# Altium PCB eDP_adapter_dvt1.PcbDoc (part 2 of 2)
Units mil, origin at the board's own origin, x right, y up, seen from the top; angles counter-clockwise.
Board outline 1964.57 x 1377.95 mil, 4 copper layers (Top Layer, Internal Plane 1, Internal Plane 2, Bottom Layer), stack 65.8 mil thick; 112 components, 78 nets, 1150 pads, 214 vias.
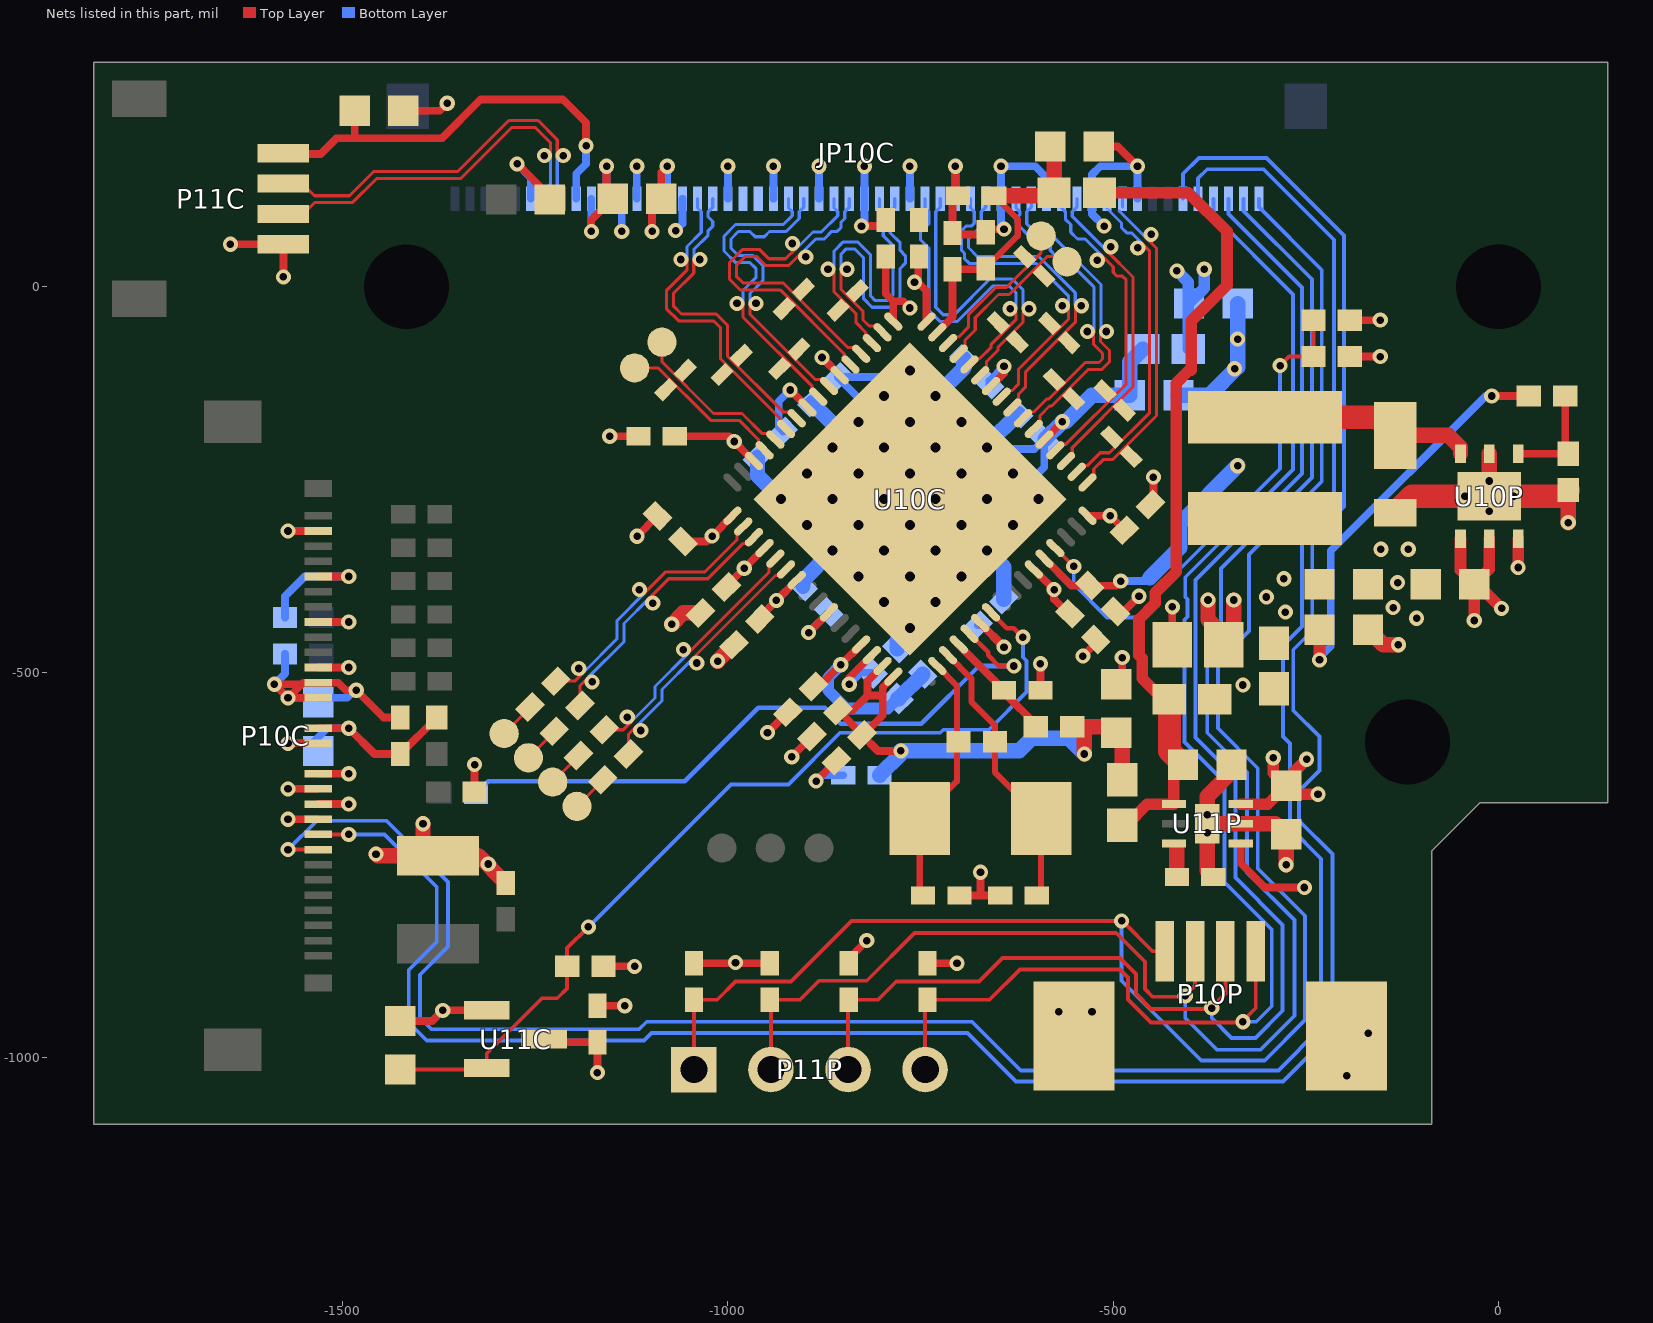
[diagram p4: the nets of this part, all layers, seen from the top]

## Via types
v1: diameter 19.68, hole 9.84, Top Layer to Bottom Layer, tented top, 176 vias
v2: diameter 25.98, hole 12.99, Top Layer to Bottom Layer, tented top, 36 vias
v3: diameter 20, hole 10, Top Layer to Bottom Layer, tented bottom, 2 vias

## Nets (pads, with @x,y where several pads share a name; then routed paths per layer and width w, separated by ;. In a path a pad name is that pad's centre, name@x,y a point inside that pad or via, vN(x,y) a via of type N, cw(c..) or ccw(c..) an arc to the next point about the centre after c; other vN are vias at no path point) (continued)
GND: C10P.1 C11P.1 C12P.2 C13P.2 C14P.1 C15P.1 C16C.2 C16P.1 C17C.1 C17P.1 C18C.1 C18P.1 C19C.1 C19P.1 C20P.1 C21P.1 C22P.1 C23C.2 C23P.1 C24P.1 C25C.2 C25P.1 C26C.2 C26P.1 C27C.2 C27P.1 C28C.2 C29C.2 C30C.2 C31C.2 C32C.2 C33C.2 C34C.2 C35C.2 C36C.2 C37C.2 C38C.2 C39C.2 C40C.2 C41C.2 C42C.2 C43C.2 C44C.2 C45C.2 C46C.2 C47C.2 C48C.2 C49C.1 C50C.1 C51C.2 D10P.1 JP10C.6 JP10C.10 JP10C.11 JP10C.16 JP10C.19 JP10C.22 JP10C.25 JP10C.28 JP10C.31 JP10C.34 JP10C.37 JP10C.40 JP10C.43 JP10C.46 P10C.2 P10C.5 P10C.8 P10C.11 P10C.15 P10C.16 P10C.18 P10C.19 P10C.20 P10C.21 P10P.MP1 P10P.MP2 P11C.1 R10P.2 R17C.2 R25C.2 R31C.2 U10C.65 U10P.2 U10P.7 U11C.1 U11P.2 U11P.PAD | length 4668.8
  Top Layer w10: v1(-1645.67,55.12) P11C.1@-1576.77,55.12 v1(-1576.77,12.8) ; v1(-1570.87,-690.94) P10C.21@-1531.5,-690.94 ; v1(-1570.87,-651.57) P10C.19@-1531.5,-651.57 ; v1(-1570.87,-592.52) P10C.16@-1531.5,-592.52 ; v1(-1570.87,-316.93) P10C.2@-1531.5,-316.93 ; P10C.20@-1531.5,-671.26 v1(-1492.13,-671.26) ; P10C.18@-1531.5,-631.89 v1(-1492.13,-631.89) ; P10C.15@-1531.5,-572.83 v1(-1492.13,-572.83) -1458.66,-606.3 C16C.2@-1425.2,-606.3 R25C.2@-1377.95,-559.06 ; P10C.11@-1531.5,-494.09 v1(-1492.13,-494.09) ; P10C.8@-1531.5,-435.04 v1(-1492.13,-435.04) ; P10C.5@-1531.5,-375.98 v1(-1492.13,-375.98) ; C51C.2@-1425.2,-952.76 -1383.86,-952.76 v1(-1370.08,-938.98) U11C.1@-1312.99,-938.98 ; C49C.1@-1421.26,228.35 -1374.02,228.35 v1(-1364.17,238.19) ; v1(-1273.62,159.45) -1231.3,117.13 C35C.2@-1231.3,113.19 ; v1(-1177.17,71.85) -1177.17,86.61 C50C.1@-1149.61,114.17 -1157.48,122.05 v1(-1157.48,156.5) ; C36C.2@-1169.29,-933.07 v1(-1133.86,-933.07) ; v1(-1153.45,-193.9) C29C.2@-1116.14,-193.9 ; v1(-1117.88,-323.65) C39C.2@-1091.51,-297.27 ; C24P.1@-1044.09,-877.95 C25P.1@-945.67,-877.95 ; v1(-948.59,-578.51) C40C.2@-922.22,-552.14 ; v1(-917.1,-610.01) C46C.2@-890.72,-583.63 ; v1(-885.6,-641.51) C45C.2@-859.22,-615.13 ; C26P.1@-843.31,-877.95 -843.31,-871.85 v1(-819.88,-848.43) ; v1(-826.67,78.74) C30C.2@-789.37,78.74 ; C27P.1@-740.94,-877.95 v1(-702.76,-877.95) ; C48C.2@-708.66,67.91 -666.34,67.91 -659.45,74.8 v1(-641.73,74.8) ; C48C.2@-708.66,69.88 -708.66,111.22 C18P.1@-701.77,118.11 -704.72,121.06 v1(-704.72,156.5) ; C18C.1@-699.52,-790.07 -672.24,-790.07 ; v1(-672.24,-759.84) -672.24,-790.07 ; C19C.1@-646.54,-790.07 -672.24,-790.07 ; C44C.2@-594.49,-523.62 v1(-594.49,-489.17) ; v1(-539.37,-479.33) -522.67,-462.63 C27C.2@-522.67,-457.65 ; C19P.1@-518.7,182.09 -494.09,182.09 v1(-468.5,156.5) ; C25C.2@-491.17,-426.15 v1(-466.59,-401.57) ; C15P.1@-488.19,-515.75 v1(-488.19,-481.3) ; C31C.2@-451.8,-282.51 -447.83,-278.54 v1(-447.83,-247.05) ; C12P.2@-423.23,-464.57 v1(-423.23,-415.35) ; R17C.2@-192.91,-43.31 v1(-153.54,-43.31)
  Top Layer w20: v1(-1456.69,-736.22) -1454.72,-738.19 C23C.2@-1375.98,-738.19 ; v1(-1395.67,-696.85) -1395.67,-718.5 C23C.2@-1375.98,-738.19 ; C34C.2@-1288.39,-773.62 -1323.82,-738.19 C23C.2@-1375.98,-738.19 ; v1(-1072.83,-437.99) -1058.04,-423.2 C41C.2@-1035.4,-423.2 ; v1(-1013.36,-485.8) C43C.2@-992.1,-464.54 ; C16P.1@-370.08,-765.75 -377.95,-757.87 v3(-377.95,-708.66) U11P.PAD@-377.95,-696.85 ; C17P.1@-346.46,-620.08 -346.46,-629.92 -377.95,-661.42 v3(-377.95,-685.04) U11P.PAD@-377.95,-696.85 ; v1(-275.59,-750) C20P.1@-275.59,-710.63 -289.37,-696.85 U11P.2@-334.65,-696.85 U11P.PAD@-377.95,-696.85 ; C11P.1@-169.29,-444.88 -149.61,-464.57 v1(-129.92,-464.57) ; U10P.7@-11.97,-271.78 v1(-11.97,-252.09) U10P.2@-11.97,-216.66 ; v1(90.55,-306.1) R10P.2@90.55,-263.78
  Top Layer w30: D10P.1@-133.86,-293.31 -112.33,-271.78 v1(-43.46,-271.78) U10P.7@-11.97,-271.78 v1(19.53,-271.78) 82.55,-271.78 R10P.2@90.55,-263.78
  Bottom Layer w10: R31C.2@-1574.8,-429.13 -1574.8,-401.57 -1549.21,-375.98 v1(-1492.13,-375.98) ; v1(-1570.87,-592.52) -1539.37,-592.52 -1519.69,-572.83 v1(-1492.13,-572.83) ; v1(-1273.62,159.45) -1255.91,141.73 JP10C.6@-1255.91,114.17 ; v1(-1177.17,71.85) JP10C.10@-1177.17,114.17 ; JP10C.11@-1157.48,114.17 v1(-1157.48,156.5) ; v1(-1067.91,72.83) -1059.06,81.69 JP10C.16@-1059.06,114.17 ; JP10C.19@-1000,114.17 v1(-1000,156.5) ; JP10C.22@-940.94,114.17 v1(-940.94,156.5) ; v1(-885.6,-641.51) -877.95,-633.86 C14P.1@-850.39,-633.86 ; JP10C.25@-881.89,114.17 v1(-881.89,156.5) ; v1(-826.67,78.74) -822.83,82.58 JP10C.28@-822.83,114.17 v1(-822.83,156.5) ; JP10C.31@-763.78,114.17 v1(-763.78,156.5) ; JP10C.34@-704.72,114.17 v1(-704.72,156.5) ; v1(-641.73,74.8) -645.67,78.74 JP10C.37@-645.67,114.17 v1(-645.67,156.5) -601.38,156.5 -586.61,141.73 JP10C.40@-586.61,114.17 ; v1(-511.81,78.74) -527.56,94.49 JP10C.43@-527.56,114.17 -527.56,145.67 -516.73,156.5 v1(-468.5,156.5) JP10C.46@-468.5,114.17
  Bottom Layer w20: C33C.2@-961.59,-221.43 -961.59,-244.82 v2(-930.81,-275.59) ; C42C.2@-902.53,-388.81 -902.53,-380.93 v2(-864,-342.4) ; C37C.2@-890.72,-150.56 -864,-177.28 v2(-864,-208.78) ; C22P.1@-780.48,-469.52 -780.48,-459.33 v2(-763.78,-442.62) ; v2(-730.37,-141.96) -693.87,-105.46 C32C.2@-693.87,-93.53 ; v2(-663.56,-342.4) -641.98,-363.98 C26C.2@-641.98,-405.74 ; v2(-663.56,-208.78) -663.56,-204.96 C38C.2@-623,-164.4 ; C23P.1@-415.35,-140.75 -375,-140.75 -338.58,-104.33 C21P.1@-338.58,-21.65
  other v1: -196.85,-1023.62 -169.29,-968.5 -570.87,-940.94 -527.56,-940.94 -990.16,-876.97 -1311.02,-749.02 -106.3,-430.12 -136.81,-416.34 -130.91,-383.86 -152.56,-340.55 -117.13,-340.55 -11.97,-291.46 -342.52,-106.3 -338.58,-67.91
  other v2: -797.19,-409.22 -730.37,-409.22 -830.59,-375.81 -763.78,-375.81 -696.97,-375.81 -797.19,-342.4 -730.37,-342.4 -897.41,-309 -830.59,-309 -763.78,-309 -696.97,-309 -630.15,-309 -864,-275.59 -797.19,-275.59 -730.37,-275.59 -663.56,-275.59 -596.75,-275.59 -897.41,-242.18 -830.59,-242.18 -763.78,-242.18 -696.97,-242.18 -630.15,-242.18 -797.19,-208.78 -730.37,-208.78 -830.59,-175.37 -763.78,-175.37 -696.97,-175.37 -797.19,-141.96 -763.78,-108.56
GPIO_PWM1: JP10C.50 P10C.23 | length 3031.4
  Top Layer w5: v1(-1570.87,-730.32) P10C.23@-1531.5,-730.32
  Bottom Layer w5: v1(-1570.87,-730.32) -1533.46,-692.91 -1442.91,-692.91 -1363.19,-772.64 -1363.19,-856.3 -1399.61,-892.72 -1399.61,-948.82 -1384.84,-963.58 -1115.16,-963.58 -1105.32,-953.74 -683.07,-953.74 -619.93,-1016.88 -285.58,-1016.88 -230.17,-961.47 -230.17,-742.27 -270.67,-701.77 -270.67,-592.52 -279.53,-583.66 -279.53,-465.55 -254.92,-440.94 -254.92,-320.87 -213.58,-279.53 -213.58,61.02 -305.12,152.56 -377.95,152.56 -389.76,140.75 JP10C.50@-389.76,114.17
I2C_ADR: R16C.2 R17C.1 U10C.13 | length 660.9
  Top Layer w5: U10C.13@-575.17,-338.92 v1(-551.18,-362.91) ; v1(-283.46,-102.36) -271.65,-90.55 R16C.2@-240.16,-90.55 R17C.1@-240.16,-43.31
  Bottom Layer w5: v1(-551.18,-362.91) -551.18,-385.83 -507.87,-429.13 -460.63,-429.13 -444.88,-413.39 -444.88,-397.64 -283.46,-236.22 v1(-283.46,-102.36)
LCD_BL_ON: JP10C.49 P10C.22 | length 3034.5
  Top Layer w5: P10C.22@-1531.5,-710.63 v1(-1492.13,-710.63)
  Bottom Layer w5: v1(-1492.13,-710.63) -1445.87,-710.63 -1377.8,-778.69 -1377.8,-850.25 -1414.22,-886.66 -1414.22,-954.87 -1390.9,-978.2 -1109.1,-978.2 -1099.26,-968.36 -689.12,-968.36 -625.98,-1031.5 -279.53,-1031.5 -215.55,-967.52 -215.55,-736.22 -258.86,-692.91 -258.86,-654.53 -232.28,-627.95 -232.28,-583.66 -266.3,-549.64 -266.3,-471.03 -241.7,-446.42 -241.7,-326.34 -200.36,-285 -200.36,66.5 -301.18,167.32 -388.78,167.32 -409.45,146.65 JP10C.49@-409.45,114.17
LCD_XM: C26P.2 JP10C.52 P10P.3 P11P.3 | length 2035.7
  Top Layer w5: P11P.3@-844.09,-1015.75 -844.09,-925.98 C26P.2@-843.31,-925.2 -805.12,-925.2 -781.5,-901.57 -674.21,-901.57 -643.7,-871.06 -491.14,-871.06 -470.47,-891.73 -470.47,-917.32 -450.79,-937.01 -374.02,-937.01 -354.33,-917.32 P10P.3@-354.33,-862.2
  Bottom Layer w5: v1(-372.05,-936.02) -372.05,-949.21 -346.46,-974.8 -315.35,-974.8 -280.12,-939.57 -280.12,-828.21 -341.54,-766.8 -341.54,-636.81 -393.31,-585.04 -393.31,-380.52 -254.92,-242.13 -254.92,-0.98 -350.39,94.49 JP10C.52@-350.39,114.17
LCD_XP: C24P.2 JP10C.54 P10P.1 P11P.1 | length 2343.1
  Top Layer w5: P11P.1@-1044.09,-1015.75 C24P.2@-1044.09,-925.2 -1013.78,-925.2 -990.16,-901.57 -918.31,-901.57 -839.57,-822.83 -488.19,-822.83 -448.82,-862.2 P10P.1@-433.07,-862.2
  Bottom Layer w5: v1(-489.17,-822.83) -489.17,-900.59 -385.83,-1003.94 -303.28,-1003.94 -250.98,-951.64 -250.98,-816.14 -312.4,-754.73 -312.4,-624.74 -364.17,-572.97 -364.17,-487.2 -323.82,-446.85 -323.82,-347.21 -229.33,-252.73 -229.33,21.65 -311.02,103.35 JP10C.54@-311.02,114.17
LCD_YM: C27P.2 JP10C.51 P10P.4 P11P.4 | length 1905
  Top Layer w5: P11P.4@-744.09,-1015.75 -744.09,-928.35 C27P.2@-740.94,-925.2 -660.43,-925.2 -621.06,-885.83 -491.14,-885.83 -480.81,-896.16 -480.81,-924.7 -450.79,-954.72 -333.66,-954.72 -314.96,-936.02 P10P.4@-314.96,-862.2
  Bottom Layer w5: JP10C.51@-370.08,114.17 -370.08,93.5 -266.73,-9.84 -266.73,-237.23 -406.5,-377 -406.5,-402.56 -403.54,-405.51 -403.54,-428.15 -407.48,-432.09 -407.48,-590.9 -355.7,-642.68 -355.7,-772.67 -294.29,-834.08 -294.29,-933.7 -314.33,-953.74 v1(-331.69,-953.74)
LCD_YP: C25P.2 JP10C.53 P10P.2 P11P.2 | length 2190.1
  Top Layer w5: P11P.2@-944.09,-1015.75 -944.09,-926.77 C25P.2@-945.67,-925.2 -906.5,-925.2 -881.89,-900.59 -819.88,-900.59 -757.87,-838.58 -496.06,-838.58 -458.66,-875.98 -458.66,-911.42 -448.82,-921.26 -408.46,-921.26 -393.7,-906.5 P10P.2@-393.7,-862.2
  Bottom Layer w5: v1(-406.5,-920.28) -406.5,-948.82 -365.16,-990.16 -308.99,-990.16 -264.76,-945.93 -264.76,-821.85 -326.18,-760.44 -326.18,-630.45 -377.95,-578.67 -377.95,-479.33 -360.24,-461.61 -360.24,-365.54 -242.13,-247.43 -242.13,9.84 -330.71,98.43 JP10C.53@-330.71,114.17
LVDS0_CLK_N: JP10C.36 R11C.2 U10C.24 | length 418.1
  Top Layer w4.02: U10C.24@-630.85,-156.58 -622.7,-148.43 -622.7,-139.11 -614.02,-130.42 -614.02,-111.02 -549.06,-46.06 v1@-549.06,-23.62
  Bottom Layer w4.02: JP10C.36@-665.35,114.17 -665.35,103.35 -671.26,97.44 -671.26,78.79 -687.83,62.21 -687.83,50.98 -676.23,39.37 -596.5,39.37 -549.21,-7.92 v1@-549.21,-23.62
  other v1: -541.34,-24.61
LVDS0_CLK_P: JP10C.35 R11C.1 U10C.25 | length 417.2
  Top Layer w4.02: U10C.25@-644.77,-142.66 -636.81,-134.7 -631.05,-134.7 -623.03,-126.69 -623.03,-107.28 -558.07,-42.32 v1@-558.07,-23.62
  Bottom Layer w4.02: JP10C.35@-685.04,114.17 -685.04,102.2 -680.28,97.44 -680.28,82.52 -684.06,78.74 -690.95,78.74 -694.88,74.8 -694.88,67.91 -696.85,65.94 -696.85,47.24 -692.91,43.31 -692.91,36.42 -686.85,30.35 -600.24,30.35 -558.23,-11.65 v1@-558.23,-23.62
  other v1: -565.94,-24.61
LVDS0_TX_0_N: JP10C.45 R14C.2 U10C.17 | length 426.9
  Top Layer w4.02: U10C.17@-533.41,-254.02 -525.27,-245.87 -525.27,-236.55 -513.13,-224.41 -500.98,-224.41 -474.41,-197.83 -443.74,-167.16 -443.74,49.99 v1@-455.24,61.49
  Bottom Layer w4.02: -492.13,98.43 v1@-455.71,62.01 ; JP10C.45@-488.19,103.35 JP10C.45@-488.19,114.17
  other v1: -450.79,67.91
LVDS0_TX_0_P: JP10C.44 R14C.1 U10C.18 | length 425.3
  Top Layer w4.02: U10C.18@-547.33,-240.1 -539.38,-232.14 -533.61,-232.14 -516.86,-215.39 -504.72,-215.39 -452.76,-163.43 -452.76,46.26 v1@-461.61,55.12
  Bottom Layer w4.02: JP10C.44@-507.87,102.2 JP10C.44@-507.87,114.17 ; JP10C.44@-505.39,98.94 -489.17,82.72 -489.17,76.77 -482.31,69.9 -476.36,69.9 v1@-462.08,55.63
  other v1: -468.19,50.51
LVDS0_TX_1_N: JP10C.42 R13C.2 U10C.19 | length 410.1
  Top Layer w4.02: U10C.19@-561.25,-226.18 -553.1,-218.03 -553.1,-208.71 -474.25,-129.85 -474.25,12.64 v1@-507.87,46.26
  Bottom Layer w4.02: JP10C.42@-547.24,114.17 -547.24,103.35 -553.15,97.44 -553.15,91.54 v1@-508.86,47.24
  other v1: -503.27,51.85
LVDS0_TX_1_P: JP10C.41 R13C.1 U10C.20 | length 411
  Top Layer w4.02: U10C.20@-575.17,-212.26 -567.21,-204.3 -561.45,-204.3 -483.27,-126.12 -483.27,8.9 -488.19,13.82 -495.12,13.82 -499.98,18.68 -499.98,25.61 v1@-514.25,39.88
  Bottom Layer w4.02: JP10C.41@-566.93,114.17 -566.93,102.2 -562.17,97.44 -562.17,87.8 -555.12,80.75 -555.12,70.87 -546.26,62.01 -536.37,62.01 v1@-515.23,40.87
  other v1: -520.67,34.45
LVDS0_TX_2_N: JP10C.39 R12C.2 U10C.22 | length 410.8
  Top Layer w4.02: U10C.22@-603.01,-184.42 -594.86,-176.27 -594.86,-166.95 -582.6,-154.69 -579.93,-154.69 -540.94,-115.7 -532.53,-107.28 -514.76,-107.28 -504.92,-97.44 -504.92,-82.68 -516.57,-71.02 v1@-516.57,-57.09
  Bottom Layer w4.02: JP10C.39@-606.3,114.17 -606.3,103.35 -612.2,97.44 -612.2,81.65 -603.39,72.83 -585.67,72.83 -515.75,2.91 v1@-515.75,-59.06
  other v1: -508.86,-58.07
LVDS0_TX_2_P: JP10C.38 R12C.1 U10C.23 | length 410.9
  Top Layer w4.02: U10C.23@-616.93,-170.5 -608.97,-162.54 -603.21,-162.54 -586.33,-145.67 -583.66,-145.67 -547.31,-109.32 -536.26,-98.27 -518.5,-98.27 -513.94,-93.71 -513.94,-86.41 -525.59,-74.76 v1@-525.59,-57.09
  Bottom Layer w4.02: JP10C.38@-625.98,114.17 -625.98,102.2 -621.22,97.44 -621.22,93.35 -625.98,88.58 -625.98,82.68 -607.13,63.82 -589.41,63.82 -581.69,56.1 -581.69,47.24 -574.8,40.35 -565.94,40.35 -524.76,-0.83 v1@-524.76,-59.06
  other v1: -533.46,-58.07
LVDS0_TX_3_N: JP10C.33 R10C.2 U10C.27 | length 413.3
  Top Layer w4.02: U10C.27@-672.61,-114.82 -664.46,-106.67 -664.46,-97.35 -649.45,-82.34 -649.45,-78.54 -616.97,-46.06 v1@-616.97,-33.46
  Bottom Layer w4.02: JP10C.33@-724.41,114.17 -724.41,103.35 -730.31,97.44 -730.31,32.68 -730.31,-26.57 -720.63,-36.26 -706.49,-36.26 -660.23,10 -631.11,10 -617.13,-3.98 v1@-617.13,-27.56
  other v1: -609.25,-28.54
LVDS0_TX_3_P: JP10C.32 R10C.1 U10C.28 | length 413.2
  Top Layer w4.02: U10C.28@-686.53,-100.9 -678.57,-92.94 -672.8,-92.94 -658.46,-78.61 -658.46,-74.8 -625.98,-42.32 v1@-625.98,-33.46
  Bottom Layer w4.02: JP10C.32@-744.09,114.17 -744.09,102.2 -739.33,97.44 -739.33,81.54 -750,70.87 -750,60.87 -739.33,50.2 -739.33,-30.31 -724.36,-45.28 -702.76,-45.28 -656.5,0.98 -634.84,0.98 -626.14,-7.72 v1@-626.14,-27.56
  other v1: -633.86,-28.54
LVDS1_CLK_N: JP10C.21
LVDS1_CLK_P: JP10C.20
LVDS1_TX0_N: JP10C.30 R18C.1 U10C.34 | length 416.2
  Top Layer w4.02: v1@-853.19,20.67 -853.19,-3.16 -824.65,-31.7 -824.65,-43.1 -816.74,-51 -807.42,-51 U10C.34@-799.27,-59.14
  Bottom Layer w4.02: v1@-853.35,22.64 -853.35,42.32 -846.46,49.21 -835.63,49.21 -823.82,37.4 -823.82,-15.75 -812.99,-26.57 -789.37,-26.57 -776.57,-13.78 -776.57,23.62 -769.69,30.51 -769.69,40.35 -776.57,47.24 -776.57,57.09 -789.37,69.88 -789.37,97.44 -783.46,103.35 JP10C.30@-783.46,114.17
  other v1: -845.47,22.64
LVDS1_TX0_P: JP10C.29 R18C.2 U10C.35 | length 416.4
  Top Layer w4.02: v1@-862.2,20.67 -862.2,-6.89 -833.66,-35.43 -833.66,-46.83 -821.15,-59.34 -821.15,-65.11 U10C.35@-813.19,-73.06
  Bottom Layer w4.02: v1@-862.36,22.64 -862.36,46.06 -850.19,58.23 -831.9,58.23 -814.8,41.14 -814.8,12.8 -814.8,-12.01 -809.26,-17.56 -793.1,-17.56 -785.59,-10.05 -785.59,53.35 -798.39,66.15 -798.39,97.44 -803.15,102.2 JP10C.29@-803.15,114.17
  other v1: -870.08,22.64
LVDS1_TX1_N: JP10C.27 R19C.1 U10C.36 | length 425.1
  Top Layer w4.02: v1@-905.04,43.82 -921.46,27.4 -950.63,27.4 -962.44,39.21 -977.56,39.21 -989.02,27.76 -989.02,13.58 -980.52,5.08 -928.5,5.08 -844.58,-78.84 -835.26,-78.84 U10C.36@-827.11,-86.98
  Bottom Layer w4.02: v1@-904.55,43.33 -885.87,62.01 -875.05,62.01 -865.2,71.85 -858.27,71.85 -853.35,76.77 -853.35,83.71 -848.43,88.63 -848.43,97.44 -842.52,103.35 JP10C.27@-842.52,114.17
  other v1: -898.94,38.7
LVDS1_TX1_P: JP10C.26 R19C.2 U10C.37 | length 427
  Top Layer w4.02: v1@-911.42,50.2 -925.2,36.42 -946.9,36.42 -958.71,48.23 -981.3,48.23 -998.03,31.5 -998.03,9.84 -984.25,-3.94 -932.23,-3.94 -848.99,-87.18 -848.99,-92.94 U10C.37@-841.03,-100.9
  Bottom Layer w4.02: v1@-910.93,49.7 -889.61,71.02 -878.78,71.02 -857.44,92.36 -857.44,97.44 -862.2,102.2 JP10C.26@-862.2,114.17
  other v1: -916.34,56.1
LVDS1_TX2_N: JP10C.24 R20C.1 U10C.39 | length 408.7
  Top Layer w4.02: v1@-971.3,-20.67 -971.3,-35.64 -886.34,-120.59 -877.02,-120.59 U10C.39@-868.87,-128.74
  Bottom Layer w4.02: v1@-971.3,-22.64 -971.3,-8.66 -954.72,7.92 -954.72,27.56 -967.52,40.35 -986.22,40.35 -996.06,50.2 -996.06,62.01 -986.38,71.69 -971.46,71.69 -964.72,64.96 -952.76,64.96 -946.02,71.69 -924.42,71.69 -907.48,88.63 -907.48,97.44 -901.57,103.35 JP10C.24@-901.57,114.17
  other v1: -963.58,-21.65
LVDS1_TX2_P: JP10C.23 R20C.2 U10C.40 | length 409.1
  Top Layer w4.02: v1@-980.32,-20.67 -980.32,-39.37 -890.75,-128.94 -890.75,-134.7 U10C.40@-882.79,-142.66
  Bottom Layer w4.02: v1@-980.32,-22.64 -980.32,-4.92 -963.74,11.65 -963.74,23.82 -971.25,31.34 -989.95,31.34 -1005.08,46.46 -1005.08,65.74 -990.11,80.71 -928.15,80.71 -916.5,92.36 -916.5,97.44 -921.26,102.2 JP10C.23@-921.26,114.17
  other v1: -988.19,-21.65
LVDS1_TX_3_N: JP10C.18 R21C.1 U10C.42 | length 407.1
  Top Layer w4.02: v1@-1044.29,34.45 -1044.29,17.76 -1070.87,-8.81 -1070.87,-24.65 -1060.24,-35.28 -1014.97,-35.28 -1000.44,-49.8 -1000.44,-90.01 -928.1,-162.35 -918.78,-162.35 U10C.42@-910.63,-170.5
  Bottom Layer w4.02: v1@-1044.13,36.42 -1044.13,48.43 -1025.59,66.97 -1025.59,72.83 -1019.69,78.74 -1019.69,84.65 -1025.59,90.55 -1025.59,97.44 -1019.69,103.35 JP10C.18@-1019.69,114.17
  other v1: -1036.42,35.43
LVDS1_TX_3_P: JP10C.17 R21C.2 U10C.43 | length 408.1
  Top Layer w4.02: v1@-1053.31,34.45 -1053.31,21.5 -1079.88,-5.08 -1079.88,-28.39 -1063.98,-44.29 -1018.7,-44.29 -1009.46,-53.53 -1009.46,-93.74 -1006.82,-96.38 -932.51,-170.7 -932.51,-176.46 U10C.43@-924.55,-184.42
  Bottom Layer w4.02: v1@-1053.15,36.42 -1053.15,52.17 -1034.61,70.71 -1034.61,97.44 -1039.37,102.2 JP10C.17@-1039.37,114.17
  other v1: -1061.02,35.43
NetC16P_2: C16P.2 U11P.6 | length 35.4
  Top Layer w20: C16P.2@-417.32,-765.75 -417.32,-730.32
NetC18C_2: C18C.2 R28C.2 U10C.2 Y10C.1 | length 330.3
  Top Layer w8: C18C.2@-746.76,-790.07 -750.98,-785.85 Y10C.1@-750.98,-689.85 -702.76,-641.63 -702.76,-517.57 U10C.2@-728.28,-492.04
NetC19C_2: C19C.2 R28C.1 U10C.3 Y10C.2 | length 364.4
  Top Layer w8: U10C.3@-714.37,-478.12 -684.06,-508.43 -684.06,-538.39 -653.54,-568.9 R28C.1@-653.54,-590.55 -653.54,-629.81 Y10C.2@-593.5,-689.85 -593.5,-784.27 C19C.2@-599.3,-790.07
NetC20C_2: C20C.2 J17C.1 | length 48.4
  Top Layer w4.02: J17C.1@-1290.35,-579.72 -1256.86,-546.23 C20C.2@-1256.86,-545.25
NetC21C_2: C21C.2 J18C.1 | length 48.4
  Top Layer w4.02: J18C.1@-1258.86,-611.22 -1225.36,-577.73 C21C.2@-1225.36,-576.74
NetC22C_1: C22C.1 J19C.1 | length 48.4
  Top Layer w4.02: J19C.1@-1195.87,-674.21 -1162.37,-640.72 C22C.1@-1162.37,-639.73
NetC24C_1: C24C.1 J20C.1 | length 48.4
  Top Layer w4.02: J20C.1@-1227.36,-642.72 -1193.87,-609.22 C24C.1@-1193.87,-608.24
NetC44C_1: C44C.1 R27C.2 U10C.4 | length 156.2
  Top Layer w10: U10C.4@-700.45,-464.2 -700.45,-464.91 C44C.1@-641.73,-523.62 -641.73,-526.57 -597.44,-570.87 R27C.2@-590.55,-570.87
NetD10P_2: D10P.2 L11P.1 U10P.3 | length 278.2
  Top Layer w20: D10P.2@-133.86,-192.91 -64.96,-192.91 -49.37,-208.5 U10P.3@-49.37,-216.66
  Top Layer w30: L11P.1@-303.15,-169.29 -157.48,-169.29 D10P.2@-133.86,-192.91
NetJ10C_1: J10C.1 R15C.2 U10C.29 | length 210.5
  Top Layer w4.02: U10C.29@-700.45,-86.98 -692.3,-78.84 -692.3,-69.51 -678.98,-56.19 -678.98,-40.15 -648.82,-10 -635,-10 -585.63,39.37 -566.93,39.37 J10C.1@-560.04,32.48
NetJ11C_1: J11C.1 R15C.1 U10C.30 | length 200.5
  Top Layer w4.02: U10C.30@-714.37,-73.06 -706.41,-65.11 -700.64,-65.11 -687.99,-52.46 -687.99,-36.42 -652.56,-0.98 -638.73,-0.98 -593.5,44.25 J11C.1@-593.5,65.94
NetJ14C_1: J14C.1 R22C.2 U10C.44 | length 214.5
  Top Layer w4.02: J14C.1@-1085.63,-71.85 -1085.63,-97.44 -1018.7,-164.37 -981.76,-164.37 -955.94,-190.19 -946.62,-190.19 U10C.44@-938.47,-198.34
NetJ16C_1: J16C.1 R22C.1 U10C.45 | length 216.3
  Top Layer w4.02: J16C.1@-1121.06,-105.32 -1090.51,-105.32 -1022.44,-173.39 -985.49,-173.39 -960.35,-198.53 -960.35,-204.3 U10C.45@-952.39,-212.26
NetR10P_1: R10P.1 R11P.2 U10P.1 | length 141.5
  Top Layer w10: U10P.1@25.43,-216.66 90.43,-216.66 86.61,-212.85 R11P.2@86.61,-141.73
NetR23C_1: R23C.1 U10C.62 | length 85.4
  Top Layer w10: v1(-842.52,-515.75) -842.52,-507.44 U10C.62@-813.19,-478.12
  Bottom Layer w10: v1(-842.52,-515.75) -827.78,-501.01 R23C.1@-812.96,-501.01
NetR29C_1: R29C.1 U10C.5 | length 860.7
  Top Layer w6: U10C.5@-686.53,-450.28 -662.4,-474.4 -662.4,-478.35 -648.62,-492.13 v1(-628.94,-492.13)
  Bottom Layer w6: R29C.1@-1326.77,-657.48 -1311.02,-641.73 -1056.1,-641.73 -960.63,-546.26 -874.02,-546.26 -853.35,-566.93 -749.02,-566.93 -674.21,-492.13 v1(-628.94,-492.13)
P1.8VA: C12P.1 C22P.2 C30C.1 C31C.1 C32C.1 C33C.1 C39C.1 C40C.1 C41C.1 C42C.1 C43C.1 L10P.1 L12P.2 R23C.2 U10C.16 U10C.26 U10C.33 U10C.41 U10C.49 U10C.52 U10C.55 U10C.58 U10C.61 | length 1028.1
  Top Layer w10: C39C.1@-1058.1,-330.68 -1027.66,-330.68 v1(-1020.52,-323.54) U10C.49@-994.15,-297.17 ; C41C.1@-1002,-389.79 -1002,-388.53 v1(-978.77,-365.3) U10C.52@-952.39,-338.92 ; C43C.1@-958.69,-431.13 -958.69,-428.74 v1(-937.01,-407.06) U10C.55@-910.63,-380.68 ; v1(-919.29,-134) U10C.41@-896.71,-156.58 ; v1(-895.25,-448.82) U10C.58@-868.87,-422.44 ; C40C.1@-888.81,-518.73 -881.64,-518.73 v1(-853.49,-490.58) U10C.61@-827.11,-464.2 ; C30C.1@-795.28,39.37 -795.28,-8.86 -785.35,-18.78 ; U10C.33@-785.35,-45.22 -785.35,-18.78 ; v1(-763.78,-27.56) -772.56,-18.78 -785.35,-18.78 ; U10C.26@-658.69,-128.74 -658.27,-128.74 -641.73,-112.2 v1(-641.73,-103.35) ; U10C.16@-533.41,-297.17 v1(-503.96,-297.17) C31C.1@-485.21,-315.92
  Top Layer w20: v1(-376.97,-406.5) -376.97,-432.09 -356.3,-452.76 C12P.1@-356.3,-464.57 -343.5,-451.77 v1(-343.5,-406.5)
  Bottom Layer w10: C33C.1@-928.18,-188.02 -934.06,-182.14 -934.06,-148.76 v1(-919.29,-134) ; v1(-895.25,-448.82) -895.25,-448.34 C42C.1@-869.12,-422.22 ; C32C.1@-660.46,-126.94 -660.46,-122.08 v1(-641.73,-103.35)
  Bottom Layer w15: v1(-853.49,-490.58) -870.08,-507.16 -870.08,-523.62 -846.46,-547.24 -792.38,-547.24 R23C.2@-779.56,-534.42
  Bottom Layer w20: R23C.2@-779.56,-534.42 -778.57,-534.42 C22P.2@-747.08,-502.92
  other v1: -331.69,-516.73
P1.8VA_DP_PLL: C14P.2 C15P.2 C45C.1 C46C.1 L13P.2 R27C.1 U10C.63 U10C.64 | length 764
  Top Layer w10: C46C.1@-857.31,-550.23 C46C.1@-856.33,-550.23 ; U10C.63@-799.27,-492.04 -818.9,-511.66 -818.9,-530.51 ; U10C.64@-785.35,-505.96 -799.21,-519.82 -799.21,-532.48 ; v1(-775.59,-602.36) -805.18,-602.36 C45C.1@-825.82,-581.72 C45C.1@-824.83,-581.72 ; C15P.2@-496.06,-570.87 C15P.2@-488.19,-578.74 ; C46C.1@-856.33,-550.23 -838.61,-550.23 -818.9,-530.51 ; C46C.1@-856.33,-550.23 C45C.1@-824.83,-581.72 ; C45C.1@-824.83,-581.72 -799.21,-556.1 -799.21,-532.48 ; -818.9,-530.51 -801.18,-530.51 -799.21,-532.48
  Top Layer w20: v1(-537.4,-606.3) -537.4,-576.77 -543.31,-570.87 C15P.2@-496.06,-570.87 ; L13P.2@-488.19,-639.76 C15P.2@-488.19,-578.74
  Bottom Layer w20: C14P.2@-803.15,-633.86 -775.59,-606.3 v1(-775.59,-602.36) -622.05,-602.36 -605.32,-585.63 -558.07,-585.63 v1(-537.4,-606.3)
P1.8VA_LVDS_PLL: C18P.2 C19P.2 C47C.1 C48C.1 L14P.2 U10C.31 | length 399.4
  Top Layer w8: C47C.1@-665.35,23.62 -665.35,24.61 -623.89,66.07 -623.89,87.47 C18P.2@-654.53,118.11
  Top Layer w10: U10C.31@-728.28,-59.14 -708.66,-39.52 C48C.1@-708.66,22.64 -666.34,22.64 C47C.1@-665.35,23.62
  Top Layer w20: C18P.2@-654.53,118.11 -580.71,118.11 L14P.2@-576.77,122.05 -576.77,177.17 C19P.2@-581.69,182.09
P1.8VA_REG: C17P.2 L10P.2 L13P.1 L14P.1 U11P.4 | length 1089.8
  Top Layer w15: L14P.1@-517.72,122.05 -402.56,122.05 -352.36,71.85 -352.36,1.97 -398.62,-44.29 -398.62,-108.27 -401.57,-108.27 -418.31,-125 -418.31,-370.08 -445.25,-397.02 -445.25,-410.42 -466.54,-431.7 -466.54,-478.35 -462.6,-482.28 -462.6,-507.87 -435.04,-535.43 L10P.2@-427.17,-535.43 ; L13P.1@-488.19,-698.82 -483.27,-698.82 -455.71,-671.26 U11P.4@-421.26,-671.26 -421.26,-631.89 C17P.2@-409.45,-620.08
  Top Layer w30: L10P.2@-427.17,-535.43 -427.17,-602.36 C17P.2@-409.45,-620.08
P1.8VD: C10P.2 C11P.2 C26C.1 C27C.1 C28C.1 C29C.1 L11P.2 L12P.1 R11P.1 U10C.6 U10C.11 U10C.32 U10C.46 | length 901.3
  Top Layer w10: C29C.1@-1068.9,-193.9 -998.59,-193.9 U10C.46@-966.31,-226.18 ; C28C.1@-751.97,39.37 -752.95,38.39 -752.95,4.92 -742.2,-5.83 U10C.32@-742.2,-45.22 ; U10C.6@-672.61,-436.36 -672.61,-436.64 v1(-641.73,-467.52) ; U10C.11@-603.01,-366.76 v1(-576.77,-393) -576.77,-405.51 -558.04,-424.24 C27C.1@-556.07,-424.24 ; v1(-8.86,-141.73) R11P.1@39.37,-141.73
  Top Layer w15: v1(-232.28,-484.25) C11P.2@-232.28,-444.88
  Bottom Layer w10: C26C.1@-675.39,-439.14 -670.11,-439.14 v1(-641.73,-467.52) ; v1@-235.24,-484.25 -217.52,-466.54 -217.52,-342.52 -16.73,-141.73 v1(-8.86,-141.73)
  other v1: -276.57,-422.24 -301.18,-402.56 -278.54,-378.94 -991.7,-200.79 -757.87,5.91
P3.3V: C13P.1 C16C.1 C17C.2 C20P.2 C21P.2 C25C.1 C36C.1 C50C.2 JP10C.12 JP10C.13 JP10C.14 JP10C.15 L15P.1 P10C.12 P10C.13 R16C.1 R24C.1 R26C.1 R30C.2 U10C.12 U10P.4 U10P.5 U10P.6 U11C.3 U11P.1 U11P.3 | length 1995.2
  Top Layer w10: P10C.13@-1531.5,-533.46 v1(-1570.87,-533.46) ; C16C.1@-1425.2,-559.06 -1446.85,-559.06 v1(-1482.28,-523.62) -1496.06,-523.62 -1505.91,-513.78 P10C.12@-1531.5,-513.78 -1551.18,-513.78 -1555.12,-517.72 ; R24C.1@-1328.74,-655.51 v1(-1328.74,-620.08) ; U11C.3@-1238.19,-976.38 -1234.25,-980.31 C36C.1@-1169.29,-980.31 v1(-1169.29,-1019.68) ; R26C.1@-1161.42,-881.89 v1(-1121.06,-881.89) ; v1(-1098.43,71.85) -1098.43,102.36 C50C.2@-1086.61,114.17 -1086.61,148.62 v1(-1078.74,156.5) ; U10C.12@-589.09,-352.84 -554.14,-387.8 -496.06,-387.8 v1(-490.16,-381.89) ; U11P.1@-334.65,-722.44 -334.65,-748.03 -303.15,-779.53 v1(-251.97,-779.53) ; R16C.1@-192.91,-90.55 v1(-153.54,-90.55) ; v1(-1570.87,-533.46) v1(-1588.58,-515.75) -1557.09,-515.75 -1555.12,-517.72 ; v1(-1570.87,-533.46) -1555.12,-517.72
  Top Layer w15: U11P.3@-334.65,-671.26 -299.21,-671.26 C20P.2@-275.59,-647.64 ; v1(-292.32,-611.22) -292.32,-630.91 C20P.2@-275.59,-647.64 ; v1(-249.02,-613.19) -275.59,-639.76 C20P.2@-275.59,-647.64 ; v1(-234.25,-658.46) -264.76,-658.46 C20P.2@-275.59,-647.64 ; U10P.4@-49.37,-326.9 -49.37,-367.95 C13P.1@-31.5,-385.83 ; v1(-31.5,-433.07) C13P.1@-31.5,-385.83 ; U10P.5@-11.97,-326.9 -11.97,-366.3 C13P.1@-31.5,-385.83 ; v1(3.94,-417.32) -27.56,-385.83 C13P.1@-31.5,-385.83 ; v1(25.43,-364.33) U10P.6@25.43,-326.9
  Bottom Layer w10: v1(-1588.58,-515.75) -1574.8,-501.97 R30C.2@-1574.8,-476.38 ; v1(-1570.87,-533.46) -1494.09,-533.46 -1484.25,-523.62 v1(-1482.28,-523.62) ; v1(-1137.8,71.85) JP10C.12@-1137.8,114.17 ; JP10C.13@-1118.11,114.17 v1(-1118.11,156.5) ; v1(-1098.43,71.85) JP10C.14@-1098.43,114.17 ; JP10C.15@-1078.74,114.17 v1(-1078.74,156.5) ; v1(-490.16,-381.89) -456.69,-381.89 -452.76,-377.95
  Bottom Layer w15: v1(-417.32,20.67) -402.56,5.91 L15P.1@-402.56,-80.71 ; C21P.2@-401.57,-21.65 -381.89,-1.97 v1(-381.89,22.64)
  Bottom Layer w20: -452.76,-377.95 -413.39,-338.58 -413.39,-307.09 v1(-338.58,-232.28)
P3.3VA: C23P.2 C37C.1 C38C.1 L15P.2 U10C.21 U10C.38 | length 1275.5
  Top Layer w10: v1(-877.95,-91.82) U10C.38@-854.95,-114.82 ; U10C.21@-589.09,-198.34 v1(-565.95,-175.19)
  Bottom Layer w10: v1(-877.95,-91.82) -857.31,-112.46 C37C.1@-857.31,-117.15 ; C38C.1@-588.56,-197.81 C38C.1@-589.6,-197.81 ; v1(-565.95,-175.19) v1@-562.06,-175.19 ; C37C.1@-857.31,-117.15 -796.32,-178.15 ; C37C.1@-857.31,-117.15 -789.34,-117.15 -772.89,-133.61 -772.89,-153.38 ; -796.32,-178.15 -796.32,-176.81 -772.89,-153.38 ; -796.32,-178.15 -775.19,-199.27 -754.39,-199.27 ; -772.89,-153.38 -752.13,-153.38 -730.32,-175.2 ; -754.39,-199.27 -730.32,-175.2 ; -754.39,-199.27 -754.39,-218.05 -729.33,-243.11 ; -730.32,-175.2 -694.39,-211.12 ; -729.33,-243.11 -697.34,-211.12 -694.39,-211.12 ; -729.33,-243.11 -708.26,-264.18 -685.44,-264.18 ; -694.39,-211.12 -663.39,-242.13 ; -685.44,-264.18 -663.39,-242.13 ; -685.44,-264.18 -685.55,-264.29 -685.55,-278.54 -685.55,-287.87 -675.84,-297.58 -654.45,-297.58 -631.89,-275.02 -631.89,-264.18 ; -663.39,-242.13 -631.89,-210.63 -602.42,-210.63 C38C.1@-589.6,-197.81 ; -663.39,-242.13 -641.34,-264.18 -631.89,-264.18 ; -631.89,-264.18 -619.49,-264.18 -589.6,-234.28 C38C.1@-589.6,-197.81
  Bottom Layer w20: C38C.1@-588.56,-197.81 v1(-565.95,-175.19) ; v1@-562.06,-175.19 -527.62,-140.75 C23P.2@-478.35,-140.75 -478.35,-97.44 L15P.2@-461.61,-80.71
RESET_N: C51C.1 R26C.2 U10C.7 U11C.2 | length 1185.1
  Top Layer w5: C51C.1@-1425.2,-1015.75 -1314.96,-1015.75 U11C.2@-1312.99,-1013.78 -1312.99,-995.08 -1241.14,-923.23 -1221.46,-923.23 -1208.66,-910.43 R26C.2@-1208.66,-881.89 -1208.66,-858.27 v1(-1181.1,-830.71)
  Top Layer w6: U10C.7@-658.69,-422.44 -638.22,-442.91 -628.94,-442.91 v1(-617.13,-454.72)
  Bottom Layer w5: v1(-1181.1,-830.71) -996.06,-645.67 -921.26,-645.67 -854.33,-578.74 -724.41,-578.74 -720.47,-574.8 -661.42,-574.8 -612.59,-525.98 -612.59,-485.36 -617.13,-480.83 v1(-617.13,-454.72)
TX2_N: C24C.2 U10C.53 | length 325.7
  Top Layer w4.02: C24C.2@-1160.46,-574.83 -1135.81,-574.83 v1@-1125.47,-564.49 ; v1@-1050.95,-474.64 -946.62,-370.31 -946.62,-360.99 U10C.53@-938.47,-352.84
  Bottom Layer w4.02: v1@-1124.49,-563.51 -1094.65,-533.67 -1094.65,-518.82 v1@-1051.49,-475.66
  other v1: -1130.59,-558.39 -1057.75,-470.79
TX2_P: C22C.2 U10C.54 | length 325
  Top Layer w4.02: C22C.2@-1128.97,-606.33 -1128.97,-580.74 v1@-1119.09,-570.87 ; v1@-1044.57,-481.02 -938.27,-374.72 -932.51,-374.72 U10C.54@-924.55,-366.76
  Bottom Layer w4.02: v1@-1118.11,-569.88 -1085.63,-537.4 -1085.63,-522.55 v1@-1045.11,-482.04
  other v1: -1113.19,-575.79 -1040.35,-488.19
TX3_N: C20C.1 U10C.50 | length 342.5
  Top Layer w4.02: C20C.1@-1223.45,-511.84 -1198.8,-511.84 v1@-1188.95,-501.99 ; v1@-1107.75,-397.17 -1080.51,-369.92 -1029.74,-369.92 -988.37,-328.56 -988.37,-319.23 U10C.50@-980.23,-311.09
  Bottom Layer w4.02: v1@-1187.48,-500.51 -1143.86,-456.9 -1143.86,-433.19 v1@-1108.58,-397.91
  other v1: -1193.58,-495.4 -1114.84,-393.03
TX3_P: C21C.1 U10C.51 | length 341.7
  Top Layer w4.02: C21C.1@-1191.96,-543.34 -1191.96,-517.75 v1@-1182.58,-508.37 ; v1@-1101.38,-403.54 -1076.77,-378.94 -1026,-378.94 -980.03,-332.96 -974.26,-332.96 U10C.51@-966.31,-325
  Bottom Layer w4.02: v1@-1181.1,-506.89 -1134.84,-460.63 -1134.84,-436.92 v1@-1102.2,-404.28
  other v1: -1176.18,-512.8 -1097.44,-410.43
USB_VID_N: JP10C.8 P11C.3 | length 491.3
  Top Layer w4.02: P11C.3@-1576.77,133.86 -1552.17,133.86 -1536.42,118.11 -1491.14,118.11 -1459.65,149.61 -1350.39,149.61 -1284.29,215.71 -1246.22,215.71 -1221.46,190.94 v1@-1221.46,169.29
  Bottom Layer w4.02: v1@-1221.46,169.29 -1221.46,131.89 -1216.54,126.97 JP10C.8@-1216.54,114.17
  other v1: -1213.58,170.28
USB_VID_P: JP10C.7 P11C.2 | length 476.3
  Top Layer w4.02: P11C.2@-1576.77,94.49 -1551.02,94.49 -1536.42,109.09 -1487.41,109.09 -1455.91,140.59 -1346.66,140.59 -1280.56,206.69 -1249.95,206.69 -1230.47,187.21 v1@-1230.47,169.29
  Bottom Layer w4.02: JP10C.7@-1236.22,114.17 -1236.22,127.13 -1230.47,132.87 v1@-1230.47,169.29
  other v1: -1238.19,170.28
USB_VID_P5V: C49C.2 JP10C.9 P11C.4 | length 575.1
  Top Layer w10: P11C.4@-1576.77,173.23 -1575.79,172.24 -1528.54,172.24 -1507.87,192.91 -1486.22,192.91 ; C49C.2@-1484.25,228.35 -1484.25,194.88 -1486.22,192.91 ; v1(-1184.06,183.07) -1184.06,212.6 -1214.57,243.11 -1320.87,243.11 -1371.06,192.91 -1486.22,192.91
  Bottom Layer w10: JP10C.9@-1196.85,114.17 -1196.85,146.65 -1184.06,159.45 v1(-1184.06,183.07)
pads on no net: JP10C.0 P10C.0 P10C.1 P10C.14 P10C.24 P10C.25 P10C.30 P11C.0 U10C.1 U11P.5

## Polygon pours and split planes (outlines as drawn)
GND on Bottom Layer "gnd" (solid, remove dead copper, pour order 6): -1929.13,-1188.98 -47.24,-1188.98 208.66,-933.07 208.66,291.34 133.86,366.14 -1842.52,366.14 -1913.39,295.28 -1905.51,287.4 -1905.51,-1173.23
GND on Top Layer "gnd" (solid, remove dead copper, pour order 4): -1897.64,-1181.1 31.5,-1181.1 232.28,-980.32 232.28,255.91 110.24,377.95 -1830.71,377.95 -1960.63,248.03 -1960.63,-1141.73 -1921.26,-1181.1
GND on Internal Plane 1 (split plane): 121.64,-649.19 -23.62,-649.19 -27.54,-649.58 -31.31,-650.72 -34.79,-652.58 -37.83,-655.08 -100.82,-718.07 -103.32,-721.12 -105.18,-724.59 -106.32,-728.36 -106.71,-732.28 -106.71,-1066.52 -1802.74,-1066.52 -1802.74,271.24 121.64,271.24
P1.8VA on Internal Plane 2 (split plane): -733.34,-34.14 -733.34,-58.07 -733.04,-59.61 -732.17,-60.91 -694.77,-98.31 -693.47,-99.18 -691.93,-99.49 -676.18,-99.49 -674.64,-99.18 -673.34,-98.31 -660.74,-85.71 -637.49,-85.71 -625.08,-98.12 -625.08,-106.61 -643.59,-125.11 -644.46,-126.42 -644.76,-127.95 -644.76,-180.12 -644.46,-181.65 -643.59,-182.96 -558.94,-267.6 -557.64,-268.47 -556.1,-268.78 -467.21,-268.78 -449.69,-286.3 -448.39,-287.17 -446.85,-287.48 -427.84,-287.48 -327.83,-387.49 -327.83,-447.83 -327.53,-449.37 -326.66,-450.67 -303.23,-474.1 -303.23,-519.99 -315.64,-532.4 -357.59,-532.4 -400.51,-489.48 -400.51,-400.59 -400.82,-399.05 -401.69,-397.75 -465.67,-333.78 -466.97,-332.91 -468.5,-332.6 -484.25,-332.6 -485.79,-332.91 -487.09,-333.78 -510.52,-357.21 -520.98,-357.21 -538.5,-339.68 -539.8,-338.81 -541.34,-338.51 -569.88,-338.51 -571.42,-338.81 -572.72,-339.68 -730.01,-496.97 -790.35,-496.97 -791.89,-497.28 -793.19,-498.15 -825.48,-530.43 -851.68,-530.43 -1037.32,-344.79 -1037.32,-306.78 -934.17,-203.63 -933.3,-202.32 -932.99,-200.79 -932.99,-128.63 -925.5,-121.14 -915.05,-121.14 -890.63,-145.55 -889.33,-146.43 -887.8,-146.73 -857.28,-146.73 -855.75,-146.43 -854.45,-145.55 -804.25,-95.36 -803.38,-94.06 -803.07,-92.52 -803.07,-43 -773.93,-13.86 -753.63,-13.86
P1.8VD on Internal Plane 2 (split plane): -657.37,-50.08 -656.06,-50.95 -654.53,-51.26 -602.06,-51.26 -584.72,-68.59 -584.72,-182.09 -584.42,-183.62 -583.55,-184.92 -568.78,-199.69 -567.48,-200.56 -565.94,-200.86 -414.06,-200.86 -213.66,-401.27 -213.66,-477.36 -213.66,-507.2 -289.06,-582.6 -403.85,-582.6 -445,-541.45 -446.3,-540.58 -447.83,-540.28 -683.07,-540.28 -684.61,-540.58 -685.91,-541.45 -717.21,-572.76 -793.31,-572.76 -794.84,-573.06 -796.15,-573.93 -811.7,-589.49 -880.23,-589.49 -1090.47,-379.24 -1090.47,-256.58 -992.24,-158.35 -991.37,-157.05 -991.06,-155.51 -991.06,-111.9 -954.05,-74.88 -920.95,-74.88 -886.7,-109.14 -885.39,-110.01 -883.86,-110.31 -870.08,-110.31 -868.54,-110.01 -867.24,-109.14 -858.38,-100.28 -857.51,-98.98 -857.21,-97.44 -857.21,-40.05 -786.72,30.43 -737.88,30.43
P3.3V on Internal Plane 2 (split plane): 121.64,-649.19 -23.62,-649.19 -27.54,-649.58 -31.31,-650.72 -34.79,-652.58 -37.83,-655.08 -100.82,-718.07 -103.32,-721.12 -105.18,-724.59 -106.32,-728.36 -106.71,-732.28 -106.71,-1066.52 -1802.74,-1066.52 -1802.74,271.24 121.64,271.24

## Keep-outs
Keep-Out Layer:
  lines w39.37: -1822.83,-1086.61 -1822.83,291.34 141.73,291.34 141.73,-669.29 -23.62,-669.29 -86.61,-732.28 -86.61,-1086.61 -885.83,-1086.61 -1822.83,-1086.61

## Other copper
Top Layer:
  rectangle net P1.8VA: -361.22,-536.42 -304.13,-493.11
  rectangle net P1.8VD: -311.02,-452.76 -229.33,-325.79
  rectangle net GND: -170.28,-437.99 -99.41,-301.18
  text "1" at -55.12,224.41 h27.56
Bottom Layer:
  text "4" at 62.99,224.41 h27.56
Internal Plane 1 (plane layer: these items are gaps in the copper):
  rectangle: 0.65,220.47 90.55,257.86
  rectangle: -62.99,220.47 -29.53,257.86
  text "2" at -23.62,224.41 h27.56
Internal Plane 2 (plane layer: these items are gaps in the copper):
  rectangle: -62.99,220.47 13.78,257.86
  rectangle: 43.96,220.47 90.55,257.86
  lines w7.87: -1094.49,-380.91 -881.89,-593.5 -810.04,-593.5 -793.31,-576.77 -715.55,-576.77 -683.07,-544.29 -447.83,-544.29 -405.51,-586.61 -287.4,-586.61 -209.65,-508.86 -209.65,-477.36 -209.65,-399.61 -412.4,-196.85 -565.94,-196.85 -580.71,-182.09 -580.71,-66.93 -600.39,-47.24 -654.53,-47.24 -736.22,34.45 -788.39,34.45 -861.22,-38.39 -861.22,-97.44 -870.08,-106.3 -883.86,-106.3 -919.29,-70.87 -955.71,-70.87 -995.08,-110.24 -995.08,-155.51 -1094.49,-254.92 -1094.49,-380.91 ; -1041.34,-346.46 -853.35,-534.45 -823.82,-534.45 -790.35,-500.98 -728.35,-500.98 -569.88,-342.52 -541.34,-342.52 -522.64,-361.22 -508.86,-361.22 -484.25,-336.61 -468.5,-336.61 -404.53,-400.59 -404.53,-491.14 -359.25,-536.42 -313.98,-536.42 -299.21,-521.65 -299.21,-472.44 -323.82,-447.83 -323.82,-385.83 -426.18,-283.46 -446.85,-283.46 -465.55,-264.76 -556.1,-264.76 -640.75,-180.12 -640.75,-127.95 -621.06,-108.27 -621.06,-96.46 -635.83,-81.69 -662.4,-81.69 -676.18,-95.47 -691.93,-95.47 -729.33,-58.07 -729.33,-32.48 -751.97,-9.84 -775.59,-9.84 -807.09,-41.34 -807.09,-92.52 -857.28,-142.72 -887.8,-142.72 -913.39,-117.13 -927.17,-117.13 -937.01,-126.97 -937.01,-200.79 -1041.34,-305.12 -1041.34,-346.46
  text "3" at 19.68,224.41 h27.56

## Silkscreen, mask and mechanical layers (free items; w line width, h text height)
Top Overlay:
  circle w7.87: c-1417.32,0 r98.43
  circle w7.87: c0,0 r98.43
  circle w7.87: c-118.11,-590.55 r98.43
  lines w7.87: -466.83,26.36 ccw(c-432.69,26.36) -432.69,-7.79 -146.83,-7.79 ccw(c-146.83,32.21) -106.83,32.21 -106.83,212.21 ccw(c-146.83,212.21) -146.83,252.21 -426.83,252.21 ccw(c-426.83,212.21) -466.83,212.21 -466.83,26.36
  text "Sutajio Ko-Usagi Pte Ltd" at -1339.57,224.41 h30
  text "eDP Adapter DVT1" at -1338.58,169.29 h30
  text "+" at -562.99,82.68 h27.56 r90
  text "-" at -519.69,27.56 h27.56 r180
  text "-" at -1106.3,-35.43 h27.56 r180
  text "2" at -1153.54,-66.93 h27.56
  text "+" at -1145.67,-74.8 h27.56 r180
  text "Designed in Singapore 03/14" at -1787.4,-192.91 h30 r270
  text "-" at -1311.02,-618.11 h27.56 r45
  text "3" at -1295.28,-633.86 h27.56 r45
  text "+" at -1275.59,-657.48 h27.56 r45
  text "-" at -1255.91,-677.17 h27.56 r45
  text "2" at -1232.28,-696.85 h27.56 r45
  text "+" at -1204.72,-724.41 h27.56 r45
Bottom Overlay:
  circle w5: c-1697.84,-349.09 r22.96
  region: -1464.57,267.72 -1799.21,267.72 -1799.21,106.3 -1464.57,106.3
  text "Apache 2.0 License" at -1628.94,-326.77 h30 r90
  text "c bunnie@kosagi.com" at -1687.99,-338.58 h30 r90
Top Solder:
  region: -763.78,-480.32 -716.45,-432.99 -763.78,-385.66 -811.11,-432.99
  region: -711.61,-428.15 -664.29,-380.82 -711.61,-333.5 -758.94,-380.82
  region: -658.46,-375 -611.14,-327.67 -658.46,-280.35 -705.79,-327.67
  region: -606.3,-322.83 -558.97,-275.51 -606.3,-228.18 -653.63,-275.51
  region: -658.46,-270.67 -611.14,-223.34 -658.46,-176.02 -705.79,-223.34
  region: -710.63,-322.83 -663.3,-275.51 -710.63,-228.18 -757.96,-275.51
  region: -763.78,-375.98 -716.45,-328.66 -763.78,-281.33 -811.11,-328.66
  region: -815.94,-428.15 -768.62,-380.82 -815.94,-333.5 -863.27,-380.82
  region: -763.78,-165.35 -716.45,-118.03 -763.78,-70.7 -811.11,-118.03
  region: -815.94,-217.52 -768.62,-170.19 -815.94,-122.87 -863.27,-170.19
  region: -869.09,-270.67 -821.77,-223.34 -869.09,-176.02 -916.42,-223.34
  region: -921.26,-322.83 -873.93,-275.51 -921.26,-228.18 -968.59,-275.51
  region: -710.63,-218.5 -663.3,-171.18 -710.63,-123.85 -757.96,-171.18
  region: -762.8,-270.67 -715.47,-223.34 -762.8,-176.02 -810.12,-223.34
  region: -815.94,-323.82 -768.62,-276.49 -815.94,-229.17 -863.27,-276.49
  region: -868.11,-375.98 -820.78,-328.66 -868.11,-281.33 -915.44,-328.66
Mechanical 3:
  drawing of 151 lines, arcs and shapes, not listed
  text "Board name: eDP Adapter DVT1" at 895.55,1594.24 h39.37
  text "Contact: bunnie@kosagi.com" at 895.55,1494.24 h39.37
  text "Silk: white" at 1908.98,1202.63 h30
  text "Soldermask: green" at 1904.06,1143.58 h30
  text "Material and thickness" at 307.36,1141.88 h50
  text "Finish: Immersion gold" at 1904.06,1090.43 h30
  text "Plate 0.5 oz" at 907.36,941.88 h30
  text "Top-bottom pair" at 1507.36,941.88 h30 r45
  text "Copper 0.5 oz" at 907.36,891.88 h30
  text "4mil = 50 ohm +/- 10%" at 3106.65,843.98 h30
  text "Total 1.0 oz" at 907.36,831.88 h30
  text "4mil width, 5mil space = 100 ohm diff +/- 10%" at 3106.65,725.87 h30
  text "Prepreg" at 507.36,491.88 h30
  text "FR-4 0.1mm" at 907.36,491.88 h30
  text "Copper 1 oz" at 907.36,341.88 h30
  text "Plane" at 3157.36,341.88 h30
  text "0.035mm" at 1027.36,291.88 h30
  text "Core" at 507.36,-108.12 h30
  text "FR-4 height as needed to meet overall height spec" at 907.36,-108.12 h30
  text "Overall height: 1.58mm +/-10%" at 357.36,-308.12 h30 r90
  text "Copper 1 oz" at 907.36,-508.12 h30
  text "0.035mm" at 1027.36,-558.12 h30
  text "Plane" at 3157.36,-558.12 h30
  text "Prepreg" at 507.36,-708.12 h30
  text "FR-4 0.1mm" at 907.36,-708.12 h30
  text "Diff pairs also mirror top side impedance traits" at 3098.95,-932.16 h30
  text "0.125mm = 50 ohm +/- 10%" at 3097.64,-1012.91 h30
  text "Copper 0.5 oz" at 907.36,-1108.12 h30
  text "Finish: Immersion gold" at 1907.01,-1143.83 h30
  text "Plate 0.5 oz" at 907.36,-1158.12 h30
  text "Soldermask: green" at 1902.09,-1206.82 h30
  text "Total 1.0oz" at 913.62,-1219.85 h30
  text "Silk: white" at 1907.01,-1269.81 h30
  text "Mech via: 8 mil hole / 18 mil pad smallest" at 901.46,-1353 h30
  text "Route: 4mil / 4mil smallest" at 901.46,-1453 h30
Drill Drawing:
  text ".LEGEND" at 502.17,-959.45 h60
  text "Drill Drawing." at 502.17,-1059.45 h60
